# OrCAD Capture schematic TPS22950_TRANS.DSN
size Custom; title: TPS22950 5V, 2A, 40-mOhm Adjustable Current Limited Load; rev: 1.0; note: Datasheet: SLVSFJ2     EVM: PSIL123A; note: Switch
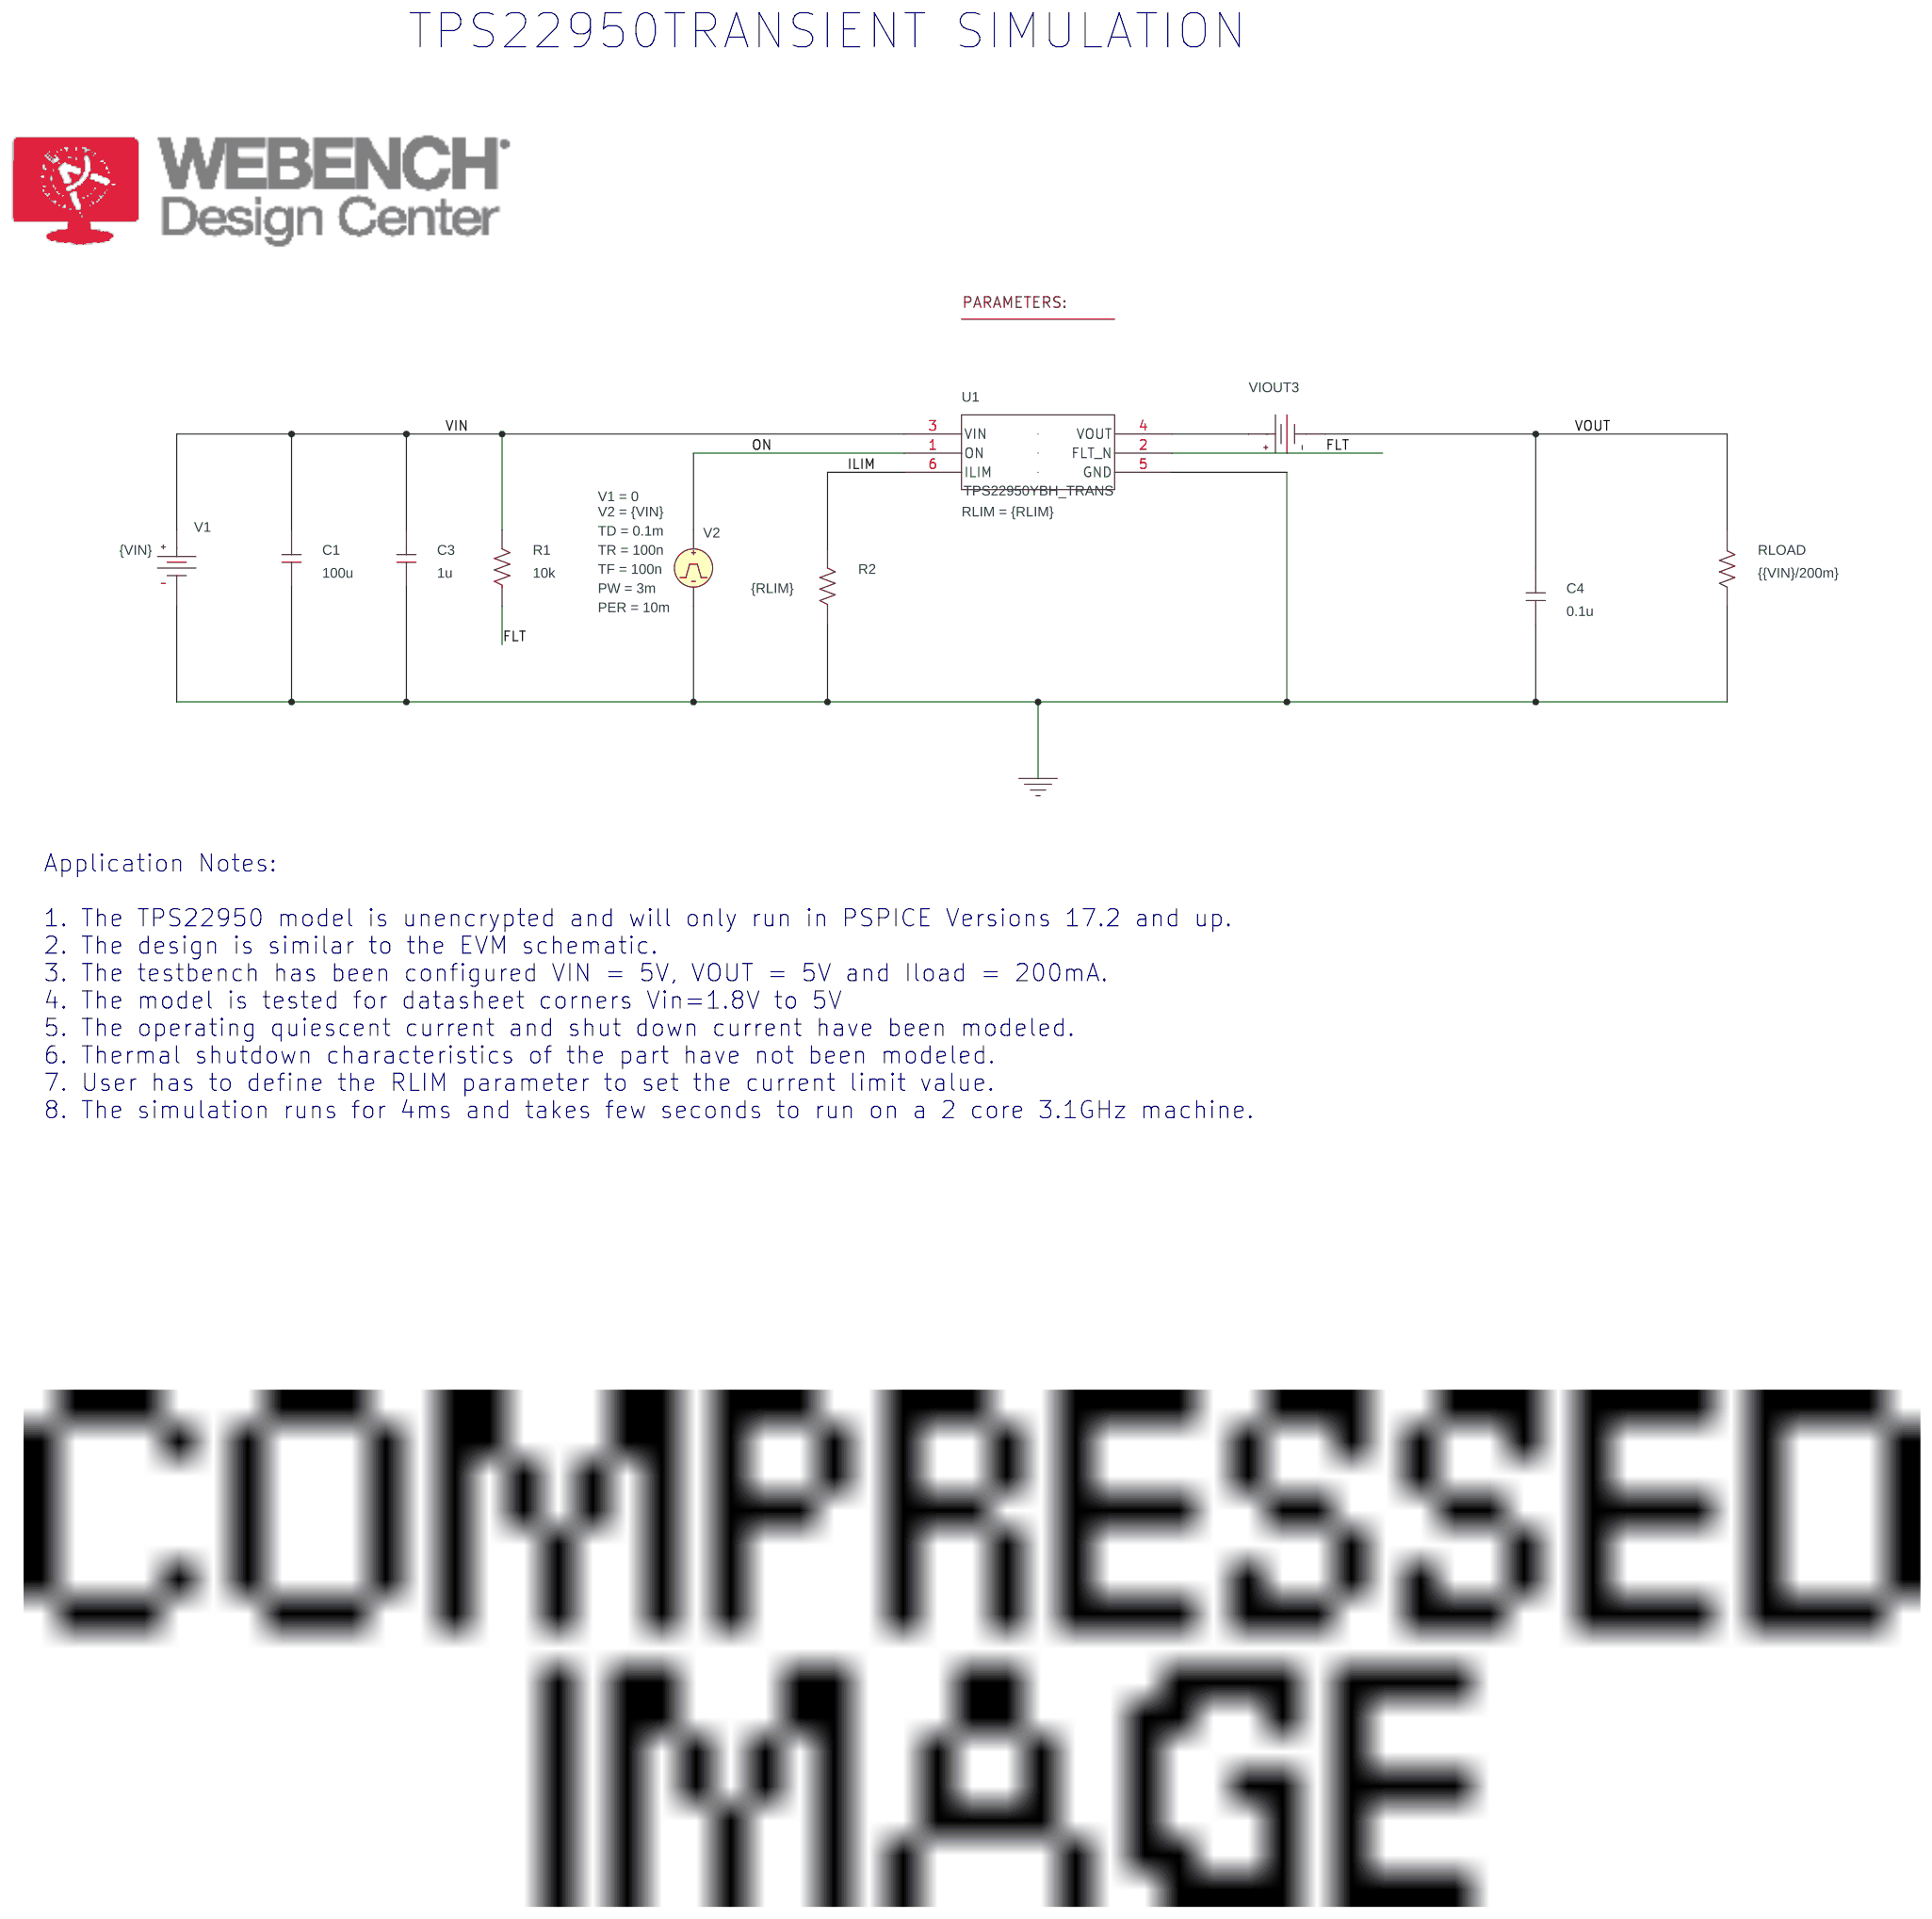
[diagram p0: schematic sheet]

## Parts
1  PARAM
C1  100u  [RAD/CK05]
C3  1u  [RAD/CK05]
C4  0.1u  [RAD/CK05]
R1  10k  [AXRC05]
R2  {RLIM}  [AXRC05]
RLOAD  {{VIN}/200m}  [AX/RC05]
U1  TPS22950YBH_TRANS  [YBH0006-IPC_A]
V1  VDC
V2  VPULSE
VIOUT3  VDC

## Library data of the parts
1 = PARAM: RLIM: 2.49k; VIN: 5
C1 C3 C4 = C
R1 R2 RLOAD = R
U1 = TPS22950YBH_TRANS: RLIM: {RLIM}
V1 = VDC: DC: {VIN}
V2 = VPULSE: PER: 10m; PW: 3m; TD: 0.1m; TF: 100n; TR: 100n; V1: 0; V2: {VIN}
VIOUT3 = VDC

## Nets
VIN: C1.2 C3.2 R1.2 U1.3(VIN) V1.0(+)
0: C1.1 C3.1 C4.1 R2.1 RLOAD.2 U1.5(GND) V1.1(-) V2.2(-)
FLT: R1.1 U1.2(FLT_N)
ILIM: R2.2 U1.6(ILIM)
ON: U1.1(ON) V2.1(+)
VOUT: C4.2 RLOAD.1 VIOUT3.1(-)
N14612247: U1.4(VOUT) VIOUT3.0(+)

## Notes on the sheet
- TPS22950TRANSIENT SIMULATION
- Application Notes:
  1. The TPS22950 model is unencrypted and will only run in PSPICE Versions 17.2 and up.
  2. The design is similar to the EVM schematic.
  3. The testbench has been configured VIN = 5V, VOUT = 5V and Iload = 200mA.
  4. The model is tested for datasheet corners Vin=1.8V to 5V
  5. The operating quiescent current and shut down current have been modeled.
  6. Thermal shutdown characteristics of the part have not been modeled.
  7. User has to define the RLIM parameter to set the current limit value.
  8. The simulation runs for 4ms and takes few seconds to run on a 2 core 3.1GHz machine.
